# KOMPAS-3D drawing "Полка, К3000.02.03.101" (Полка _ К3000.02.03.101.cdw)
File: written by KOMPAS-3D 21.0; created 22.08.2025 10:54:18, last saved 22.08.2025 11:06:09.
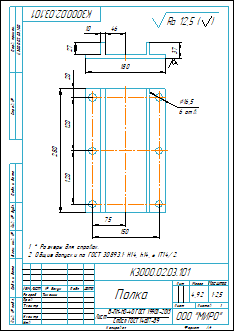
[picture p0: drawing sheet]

Sheet 1: A4, portrait

Document properties: Автор: Lutik; Знак неуказанной шероховатости: 4; Параметр неуказанной шероховатости: Ra 12,5; Масса: 4.923917

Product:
- Part/product: Полка  | designation К3000.02.03.101
    Материал: Лист$dБ-ПН-НО-40 ГОСТ 19903-2015;Ст3сп ГОСТ 14637-89$ (density 7850 kg/m3)
    Масса: 4.923917

Title block, sheet 1: Наименование: Полка; designation: К3000.02.03.101; Материал: Лист Б-ПН-НО-40 ГОСТ 19903-2015 Ст3сп ГОСТ 14637-89; Масса: 4,92; Количество листов документа: 1; organisation: ООО "МИРО"; Форматы листов документа: A4; stored path: C:\Users\Lutik\YandexDisk\Документы\Новая папка\Бабка задняя\2D\Опора_К3000.02.03.000\Полка _ К3000.02.03.101.cdw; Разработал: Тимонин

Views: Вид 1, Слева, Проекционный вид 2
Referenced files in C:\Users\Lutik\YandexDisk\Документы\Новая папка\Бабка задняя\3D\: Полка_30.m3d
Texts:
  Ra 12,5
  Ra 12,5 ( )
  К3000.02.03.101 Полка
Dimensions and other numbers on the sheet: 37; 46; 10; 27; 180; 20; 120; 280; 75; 150; 16,5; 6 отв.; 1:2,5; 1; 4,92

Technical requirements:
  * Размеры для справок.
  Общие допуски по ГОСТ 30893.1: Н14, h14, ± IT14/2.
